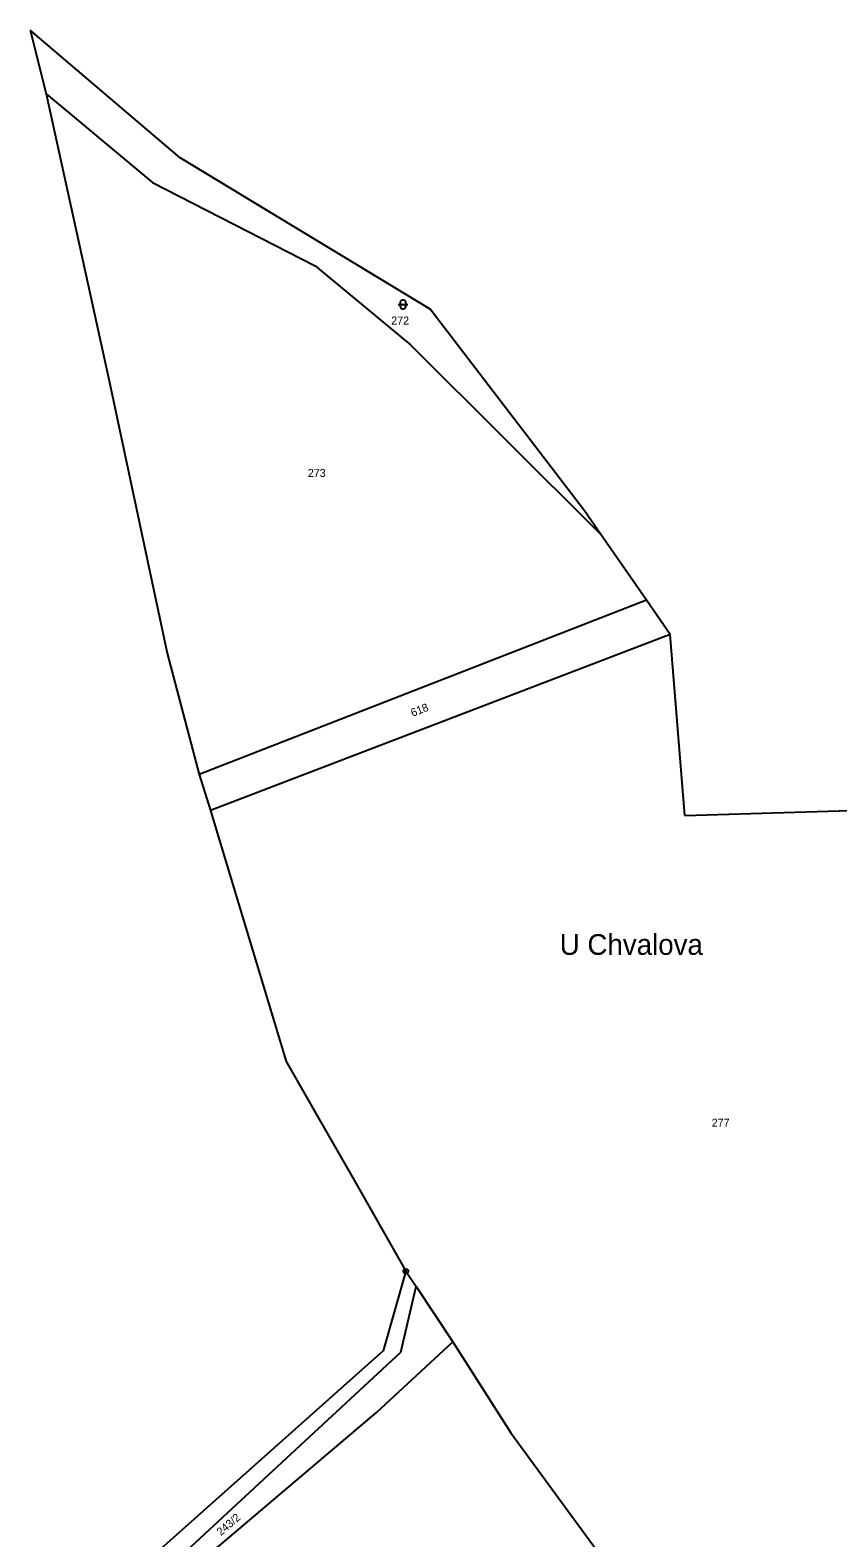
# Model space of a CAD drawing. Extents: x -794421 to -792735, y -1117671 to -1115559.
# Drawn here: x -794264.2 to -794092.7, y -1115881.2 to -1115560.8 of the extents above; entities that cross this region are included whole.
import ezdxf

# ---------------------------------------------------------------- set-up
doc = ezdxf.new("R2010")
doc.units = 0
for name, color, linetype in [('Vrstva 1', 7, 'Continuous'), ('Vrstva 14', 7, 'Continuous'), ('Vrstva 23', 7, 'Continuous'), ('Vrstva 28', 7, 'Continuous'), ('Vrstva 3', 7, 'Continuous'), ('Vrstva 39', 7, 'Continuous'), ('Vrstva 4', 7, 'Continuous')]:
    doc.layers.add(name, color=color, linetype=linetype)

msp = doc.modelspace()

# ---------------------------------------------------------------- linework, layer by layer
at = {"layer": 'Vrstva 1'}
for p, q in [((-794260.82, -1115574.3), (-794238.28, -1115593.18)), ((-794238.28, -1115593.18), (-794203.67, -1115610.85)), ((-794203.67, -1115610.85), (-794183.43, -1115627.68)), ((-794183.43, -1115627.68), (-794143.06, -1115667.94)), ((-794133.35, -1115681.91), (-794228.33, -1115718.98)), ((-794128.32, -1115689.21), (-794225.91, -1115726.66)), ((-794184.42, -1115824.55), (-794182.27, -1115827.8)), ((-794185.54, -1115841.76), (-794182.27, -1115827.8)), ((-794182.27, -1115827.8), (-794174.48, -1115839.59)), ((-794236.07, -1115888.59), (-794185.54, -1115841.76)), ((-794190.68, -1115854.56), (-794174.48, -1115839.59)), ((-794174.48, -1115839.59), (-794162.16, -1115858.87)), ((-794230.96, -1115888.7), (-794190.68, -1115854.56)), ((-794162.16, -1115858.87), (-794134.99, -1115895.95))]:
    msp.add_line(p, q, dxfattribs=at)
at = {"layer": 'Vrstva 23'}
for p, q in [((-794185.35, -1115618.18), (-794185.15, -1115618.08)), ((-794185.15, -1115618.08), (-794184.95, -1115618.08)), ((-794184.95, -1115618.08), (-794184.75, -1115618.18)), ((-794186.05, -1115619.08), (-794184.05, -1115619.08)), ((-794185.55, -1115618.48), (-794185.45, -1115618.28)), ((-794185.55, -1115619.68), (-794185.55, -1115618.48)), ((-794185.45, -1115619.88), (-794185.55, -1115619.68)), ((-794185.45, -1115618.28), (-794185.35, -1115618.18)), ((-794185.35, -1115619.98), (-794185.45, -1115619.88)), ((-794185.15, -1115620.08), (-794185.35, -1115619.98)), ((-794184.95, -1115620.08), (-794185.15, -1115620.08)), ((-794184.75, -1115619.98), (-794184.95, -1115620.08)), ((-794184.75, -1115618.18), (-794184.65, -1115618.28)), ((-794184.65, -1115619.88), (-794184.75, -1115619.98)), ((-794184.65, -1115618.28), (-794184.55, -1115618.48)), ((-794184.55, -1115619.68), (-794184.65, -1115619.88)), ((-794184.55, -1115618.48), (-794184.55, -1115619.68))]:
    msp.add_line(p, q, dxfattribs=at)
at = {"layer": 'Vrstva 28'}
for radius in [0.5, 0.01]:
    msp.add_circle((-794184.42, -1115824.55), radius, dxfattribs=at)
at = {"layer": 'Vrstva 3'}
for p, q in [((-794232.41, -1115587.92), (-794264.24, -1115560.78)), ((-794264.24, -1115560.78), (-794260.82, -1115574.3)), ((-794179.3, -1115620.06), (-794232.41, -1115587.92)), ((-794146.51, -1115662.97), (-794179.3, -1115620.06)), ((-794143.06, -1115667.94), (-794146.51, -1115662.97)), ((-794133.35, -1115681.91), (-794143.06, -1115667.94)), ((-794128.32, -1115689.21), (-794133.35, -1115681.91)), ((-794125.16, -1115727.68), (-794128.32, -1115689.21)), ((-794125.16, -1115727.68), (-794046.2, -1115725.36))]:
    msp.add_line(p, q, dxfattribs=at)
at = {"layer": 'Vrstva 4'}
for p, q in [((-794260.82, -1115574.3), (-794247.43, -1115635.33)), ((-794247.43, -1115635.33), (-794235.15, -1115693.18)), ((-794235.15, -1115693.18), (-794228.33, -1115718.98)), ((-794228.33, -1115718.98), (-794225.91, -1115726.66)), ((-794225.91, -1115726.66), (-794224.92, -1115729.94)), ((-794224.92, -1115729.94), (-794209.84, -1115779.96)), ((-794209.84, -1115779.96), (-794203.34, -1115791.36)), ((-794203.34, -1115791.36), (-794195.72, -1115804.73)), ((-794195.72, -1115804.73), (-794184.42, -1115824.55)), ((-794184.42, -1115824.55), (-794189.23, -1115841.46)), ((-794189.23, -1115841.46), (-794241.68, -1115888.13))]:
    msp.add_line(p, q, dxfattribs=at)

# ---------------------------------------------------------------- texts
at = {"layer": 'Vrstva 14'}
for s, p in [('272', (-794187.553, -1115623.35)), ('273', (-794205.263, -1115655.73)), ('277', (-794119.47, -1115793.83))]:
    msp.add_text(s, height=1.7, dxfattribs=at).set_placement(p)
for s, rotation, p in [('618', 21.40362, (-794182.994, -1115706.729)), ('243/2', 40.63986, (-794223.74, -1115880.867))]:
    msp.add_text(s, height=1.7, rotation=rotation, dxfattribs=at).set_placement(p)
at = {"layer": 'Vrstva 39'}
msp.add_text('U Chvalova', height=4.4, dxfattribs=at).set_placement((-794151.76, -1115757.31))

doc.saveas('drawing.dxf')
